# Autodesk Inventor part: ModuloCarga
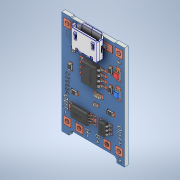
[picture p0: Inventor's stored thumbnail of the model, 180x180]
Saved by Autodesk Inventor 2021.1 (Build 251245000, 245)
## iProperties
Created: 2021-03
Part Number: ModuloCarga
Material: Genérico
Description: CATIA V5 STEP Exchange
Document SubType Name: Modeling
Designer: Ricardo
Authority: none
Density: 1 g/cm^3
Appearance: Valor por defecto
Company: none
Title: S:\DATA\M\PROJEKTY\Nabijecka 3x 18650\_pro GrabCadCommunity\Charger module_TC4056A_5V1A_USB Micro.stp
Author: none
Sending System: CATIA V5 STEP AP214
Preprocessor: CATIA Version 5 Release 19 SP 9 (IN-10)
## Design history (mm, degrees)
node "Charger module_TC4056A_5V1A_USB Micro.stp"
node "Sólido1"
feature "PCB"
node "Sólido2"
feature "PCB Cu.1"
node "Sólido3"
feature "PCB Cu.2"
node "Sólido4"
feature "PCB Cu.3"
node "Sólido5"
feature "PCB Cu.4"
node "Sólido6"
feature "PCB Cu.5"
node "Sólido7"
feature "PCB Cu.6"
node "Sólido8"
feature "PCB Cu.7"
node "Sólido9"
feature "PCB Cu.8"
node "Sólido10"
feature "PCB Cu.9"
node "Sólido11"
feature "PCB Cu.10"
node "Sólido12"
feature "PCB Cu.11"
node "Sólido13"
feature "PCB Cu.12"
node "Sólido14"
feature "PCB Cu.13"
node "Sólido15"
feature "PCB Cu.14"
node "Sólido16"
feature "PCB Cu.15"
node "Sólido17"
feature "PCB Cu.16"
node "Sólido18"
feature "PCB Cu.17"
node "Sólido19"
feature "PCB Cu.18"
node "Sólido20"
feature "PCB Cu.19"
node "Sólido21"
feature "PCB Cu.20"
node "Sólido22"
feature "PCB Cu.21"
node "Sólido23"
feature "PCB Cu.22"
node "Sólido24"
feature "PCB Cu.23"
node "Sólido25"
feature "PCB Cu.24"
node "Sólido26"
feature "PCB Cu.25"
node "Sólido27"
feature "PCB Cu.26"
node "Sólido28"
feature "PCB Cu.27"
node "Sólido29"
feature "PCB Cu.28"
node "Sólido30"
feature "PCB Cu.29"
node "Sólido31"
feature "PCB Cu.30"
node "Sólido32"
feature "PCB Cu.31"
node "Sólido33"
feature "PCB Cu.32"
node "Sólido34"
feature "PCB Cu.33"
node "Sólido35"
feature "PCB Cu.34"
node "Sólido36"
feature "PCB Cu.35"
node "Sólido37"
feature "PCB Cu.36"
node "Sólido38"
feature "PCB Cu.37"
node "Sólido39"
feature "PCB Cu.38"
node "Sólido40"
feature "PCB Cu.39"
node "Sólido41"
feature "PCB Cu.40"
node "Sólido42"
feature "PCB Cu.41"
node "Sólido43"
feature "PCB Cu.42"
node "Sólido44"
feature "PCB Cu.43"
node "Sólido45"
feature "PCB Cu.44"
node "Sólido46"
feature "PCB Cu.45"
node "Sólido47"
feature "PCB Cu.46"
node "Sólido48"
feature "PCB Cu.47"
node "Sólido49"
feature "PCB Cu.48"
node "Sólido50"
feature "PCB Cu.49"
node "Sólido51"
feature "PCB Cu.50"
node "Sólido52"
feature "PCB Cu.51"
node "Sólido53"
feature "PCB Cu.52"
node "Sólido54"
feature "PCB Cu.53"
node "Sólido55"
feature "PCB text.1"
node "Sólido56"
feature "PCB text.2"
node "Sólido57"
feature "PCB text.3"
node "Sólido58"
feature "PCB text.4"
node "Sólido59"
feature "PCB text.5"
node "Sólido60"
feature "PCB text.6"
node "Sólido61"
feature "PCB text.7"
node "Sólido62"
feature "PCB text.8"
node "Sólido63"
feature "PCB text.9"
node "Sólido64"
feature "PCB text.10"
node "Sólido65"
feature "PCB text.11"
node "Sólido66"
feature "PCB text.12"
node "Sólido67"
feature "PCB text.13"
node "Sólido68"
feature "PCB text.14"
node "Sólido69"
feature "PCB text.15"
node "Sólido70"
feature "PCB text.16"
node "Sólido71"
feature "PCB text.17"
node "Sólido72"
feature "PCB text.18"
node "Sólido73"
feature "PCB text.19"
node "Sólido74"
feature "PCB text.20"
node "Sólido75"
feature "PCB text.21"
node "Sólido76"
feature "TC4056A CL4056A"
node "Sólido77"
feature "TC4056A CL4056A pins.1"
node "Sólido78"
feature "TC4056A CL4056A pins.2"
node "Sólido79"
feature "TC4056A CL4056A pins.3"
node "Sólido80"
feature "TC4056A CL4056A pins.4"
node "Sólido81"
feature "TC4056A CL4056A pins.5"
node "Sólido82"
feature "TC4056A CL4056A pins.6"
node "Sólido83"
feature "TC4056A CL4056A pins.7"
node "Sólido84"
feature "TC4056A CL4056A pins.8"
node "Sólido85"
feature "8205A"
node "Sólido86"
feature "8205A pins.1"
node "Sólido87"
feature "8205A pins.2"
node "Sólido88"
feature "8205A pins.3"
node "Sólido89"
feature "8205A pins.4"
node "Sólido90"
feature "8205A pins.5"
node "Sólido91"
feature "8205A pins.6"
node "Sólido92"
feature "8205A pins.7"
node "Sólido93"
feature "8205A pins.8"
node "Sólido94"
feature "DW01A"
node "Sólido95"
feature "DW01A pins.1"
node "Sólido96"
feature "DW01A pins.2"
node "Sólido97"
feature "DW01A pins.3"
node "Sólido98"
feature "DW01A pins.4"
node "Sólido99"
feature "DW01A pins.5"
node "Sólido100"
feature "DW01A pins.6"
node "Sólido101"
feature "USB Micro (GCT USB3065-30-01-A)"
node "Sólido102"
feature "LED 2 Blue SMD housing"
node "Sólido103"
feature "LED 2 Blue SMD cover"
node "Sólido104"
feature "LED 2 Blue SMD marking.1"
node "Sólido105"
feature "LED 2 Blue SMD marking.2"
node "Sólido106"
feature "LED 2 Blue SMD base.1"
node "Sólido107"
feature "LED 2 Blue SMD base.2"
node "Sólido108"
feature "LED 1 Red SMD housing"
node "Sólido109"
feature "LED 1 Red SMD cover"
node "Sólido110"
feature "LED 1 Red SMD marking.1"
node "Sólido111"
feature "LED 1 Red SMD marking.2"
node "Sólido112"
feature "LED 1 Red SMD base.1"
node "Sólido113"
feature "LED 1 Red SMD base.2"
node "Sólido114"
feature "R2 SMD 102.1"
node "Sólido115"
feature "R2 SMD 102.2"
node "Sólido116"
feature "R2 SMD 102"
node "Sólido117"
feature "R2 SMD 102:1"
node "Sólido118"
feature "R1 SMD 102.1"
node "Sólido119"
feature "R1 SMD 102.2"
node "Sólido120"
feature "R1 SMD 102"
node "Sólido121"
feature "R1 SMD 102:1"
node "Sólido122"
feature "R5 SMD 101.1"
node "Sólido123"
feature "R5 SMD 101.2"
node "Sólido124"
feature "R5 SMD 101"
node "Sólido125"
feature "R5 SMD 101:1"
node "Sólido126"
feature "R6 SMD 102.1"
node "Sólido127"
feature "R6 SMD 102.2"
node "Sólido128"
feature "R6 SMD 102"
node "Sólido129"
feature "R6 SMD 102:1"
node "Sólido130"
feature "R3 SMD 122.1"
node "Sólido131"
feature "R3 SMD 122.2"
node "Sólido132"
feature "R3 SMD 122"
node "Sólido133"
feature "R3 SMD 122:1"
node "Sólido134"
feature "C3 SMD.1"
node "Sólido135"
feature "C3 SMD.2"
node "Sólido136"
feature "C3 SMD"
node "Sólido137"
feature "C2 SMD.1"
node "Sólido138"
feature "C2 SMD.2"
node "Sólido139"
feature "C2 SMD"
node "Sólido140"
feature "C1 SMD.1"
node "Sólido141"
feature "C1 SMD.2"
node "Sólido142"
feature "C1 SMD"
